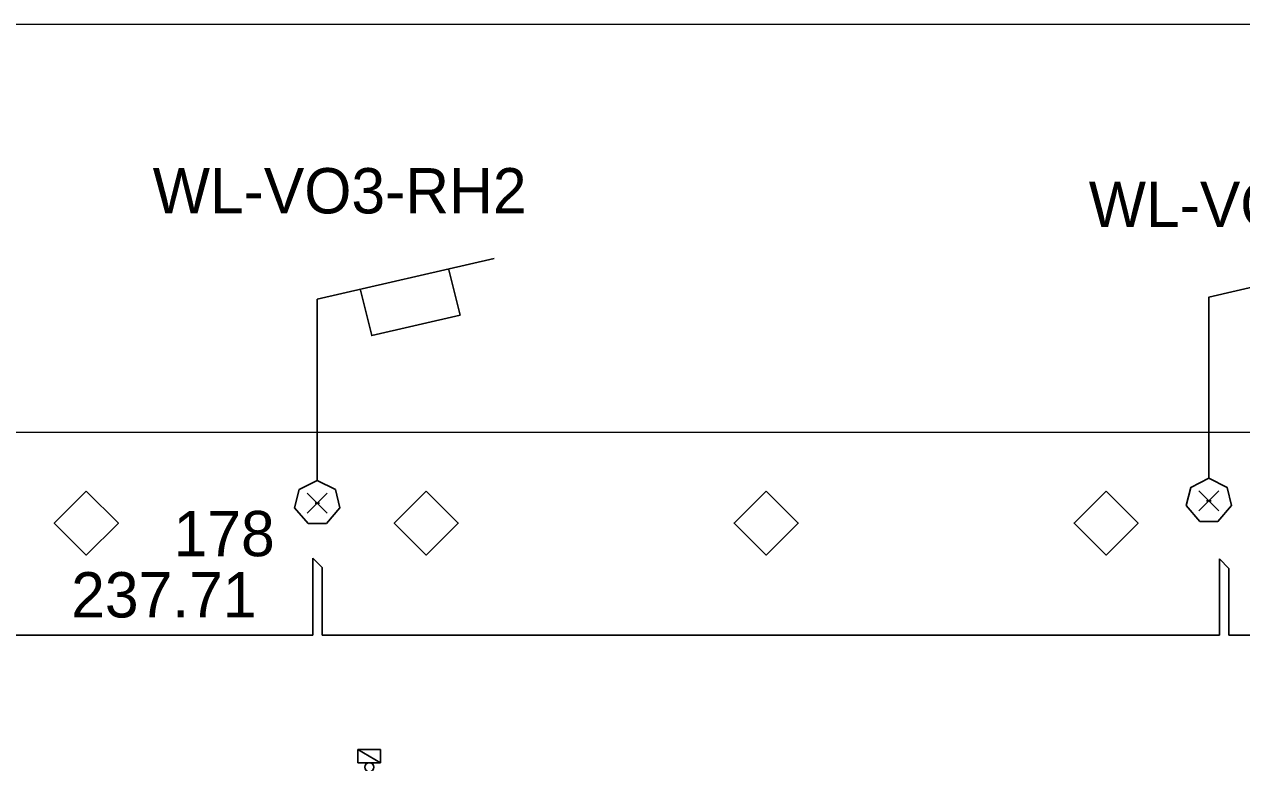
# Model space of a CAD drawing. Extents: x -264222 to -263592, y -1242345 to -1242048.
# Drawn here: x -263898.44 to -263871.58, y -1242271.27 to -1242254.98 of the extents above; entities that cross this region are included whole.
import ezdxf

# ---------------------------------------------------------------- set-up
doc = ezdxf.new("R2010")
doc.units = 0
for name, color, linetype in [('BOD_CISLO', 7, 'Continuous'), ('BOD_SYMBOL', 7, 'Continuous'), ('BOD_VYSKA', 7, 'Continuous'), ('KFA_2D_SITUACIA_DSP', 7, 'Continuous'), ('KFA_SO_62-1_VO_LAMPY_MERANE', 7, 'Continuous'), ('KFA_SO_62-1_VO_POPIS_LAMP_PROJEKT', 7, 'Continuous'), ('KFA_SO_62-1_VO_TRASA_KABLOV_PROJEKT', 7, 'Continuous')]:
    doc.layers.add(name, color=color, linetype=linetype)

msp = doc.modelspace()

# ---------------------------------------------------------------- linework, layer by layer
at = {"layer": 'BOD_SYMBOL'}
for p, q in [((-263892.193, -1242265.77), (-263891.751, -1242265.328)), ((-263891.751, -1242265.77), (-263892.193, -1242265.328)), ((-263872.521, -1242265.72), (-263872.079, -1242265.278)), ((-263872.079, -1242265.72), (-263872.521, -1242265.278))]:
    msp.add_line(p, q, dxfattribs=at)
at = {"layer": 'KFA_2D_SITUACIA_DSP'}
for p, q in [((-263891.074, -1242270.983), (-263890.574, -1242270.983)), ((-263891.074, -1242271.273), (-263891.074, -1242270.983)), ((-263891.074, -1242270.983), (-263890.574, -1242271.273)), ((-263891.074, -1242270.983), (-263890.574, -1242271.273)), ((-263890.574, -1242270.983), (-263891.074, -1242270.983)), ((-263890.574, -1242270.983), (-263890.574, -1242271.273)), ((-263890.574, -1242271.273), (-263890.574, -1242270.983)), ((-263890.574, -1242271.273), (-263891.074, -1242271.273))]:
    msp.add_line(p, q, dxfattribs=at)
msp.add_lwpolyline([(-263854.468, -1242263.985), (-263917.08, -1242263.982), (-263901.868, -1242254.982), (-263854.468, -1242254.985), (-263854.468, -1242263.985)], dxfattribs=at)
for points in [[(-263897.068, -1242265.279), (-263896.361, -1242265.986), (-263897.068, -1242266.693), (-263897.775, -1242265.986)], [(-263897.068, -1242265.279), (-263896.361, -1242265.986), (-263897.068, -1242266.693), (-263897.775, -1242265.986)], [(-263889.568, -1242265.279), (-263888.861, -1242265.986), (-263889.568, -1242266.693), (-263890.275, -1242265.986)], [(-263882.068, -1242265.279), (-263881.361, -1242265.986), (-263882.068, -1242266.693), (-263882.775, -1242265.986)], [(-263874.568, -1242265.279), (-263873.861, -1242265.986), (-263874.568, -1242266.693), (-263875.275, -1242265.986)]]:
    msp.add_lwpolyline(points, close=True, dxfattribs=at)
msp.add_circle((-263890.824, -1242271.373), 0.1, dxfattribs=at)
at = {"layer": 'KFA_SO_62-1_VO_LAMPY_MERANE'}
for p, q in [((-263872.35, -1242265.499), (-263872.25, -1242265.499)), ((-263872.3, -1242265.499), (-263872.3, -1242265.499)), ((-263892.022, -1242265.549), (-263891.922, -1242265.549)), ((-263891.972, -1242265.549), (-263891.972, -1242265.549))]:
    msp.add_line(p, q, dxfattribs=at)
for points in [[(-263872.3, -1242264.999), (-263872.7, -1242265.199), (-263872.8, -1242265.599), (-263872.5, -1242265.949), (-263872.1, -1242265.949), (-263871.8, -1242265.599), (-263871.9, -1242265.199), (-263872.3, -1242264.999), (-263872.3, -1242260.999), (-263868.4, -1242260.099)], [(-263891.972, -1242265.049), (-263892.372, -1242265.249), (-263892.472, -1242265.649), (-263892.172, -1242265.999), (-263891.772, -1242265.999), (-263891.472, -1242265.649), (-263891.572, -1242265.249), (-263891.972, -1242265.049), (-263891.972, -1242261.049), (-263888.072, -1242260.149)], [(-263889.072, -1242260.399), (-263888.822, -1242261.399), (-263890.772, -1242261.849), (-263891.022, -1242260.849)]]:
    msp.add_lwpolyline(points, dxfattribs=at)
at = {"layer": 'KFA_SO_62-1_VO_TRASA_KABLOV_PROJEKT'}
for p, q in [((-263892.068, -1242268.463), (-263892.068, -1242266.761)), ((-263892.068, -1242266.761), (-263891.863, -1242266.963)), ((-263872.068, -1242268.463), (-263872.068, -1242266.772)), ((-263872.068, -1242266.772), (-263871.858, -1242266.992)), ((-263891.863, -1242266.963), (-263891.863, -1242268.463)), ((-263871.858, -1242266.992), (-263871.858, -1242268.463)), ((-263909.374, -1242268.463), (-263892.068, -1242268.463)), ((-263891.863, -1242268.463), (-263872.068, -1242268.463)), ((-263871.858, -1242268.463), (-263854.568, -1242268.463))]:
    msp.add_line(p, q, dxfattribs=at)

# ---------------------------------------------------------------- texts
at = {"layer": 'BOD_CISLO'}
msp.add_text('178', height=1, dxfattribs=at).set_placement((-263895.142, -1242266.718))
at = {"layer": 'BOD_VYSKA'}
msp.add_text('237.71', height=1, dxfattribs=at).set_placement((-263897.402, -1242268.069))
at = {"layer": 'KFA_SO_62-1_VO_POPIS_LAMP_PROJEKT'}
for p in [(-263895.602, -1242259.154), (-263874.95, -1242259.454)]:
    msp.add_text('WL-VO3-RH2', height=1, dxfattribs=at).set_placement(p)

doc.saveas('drawing.dxf')
